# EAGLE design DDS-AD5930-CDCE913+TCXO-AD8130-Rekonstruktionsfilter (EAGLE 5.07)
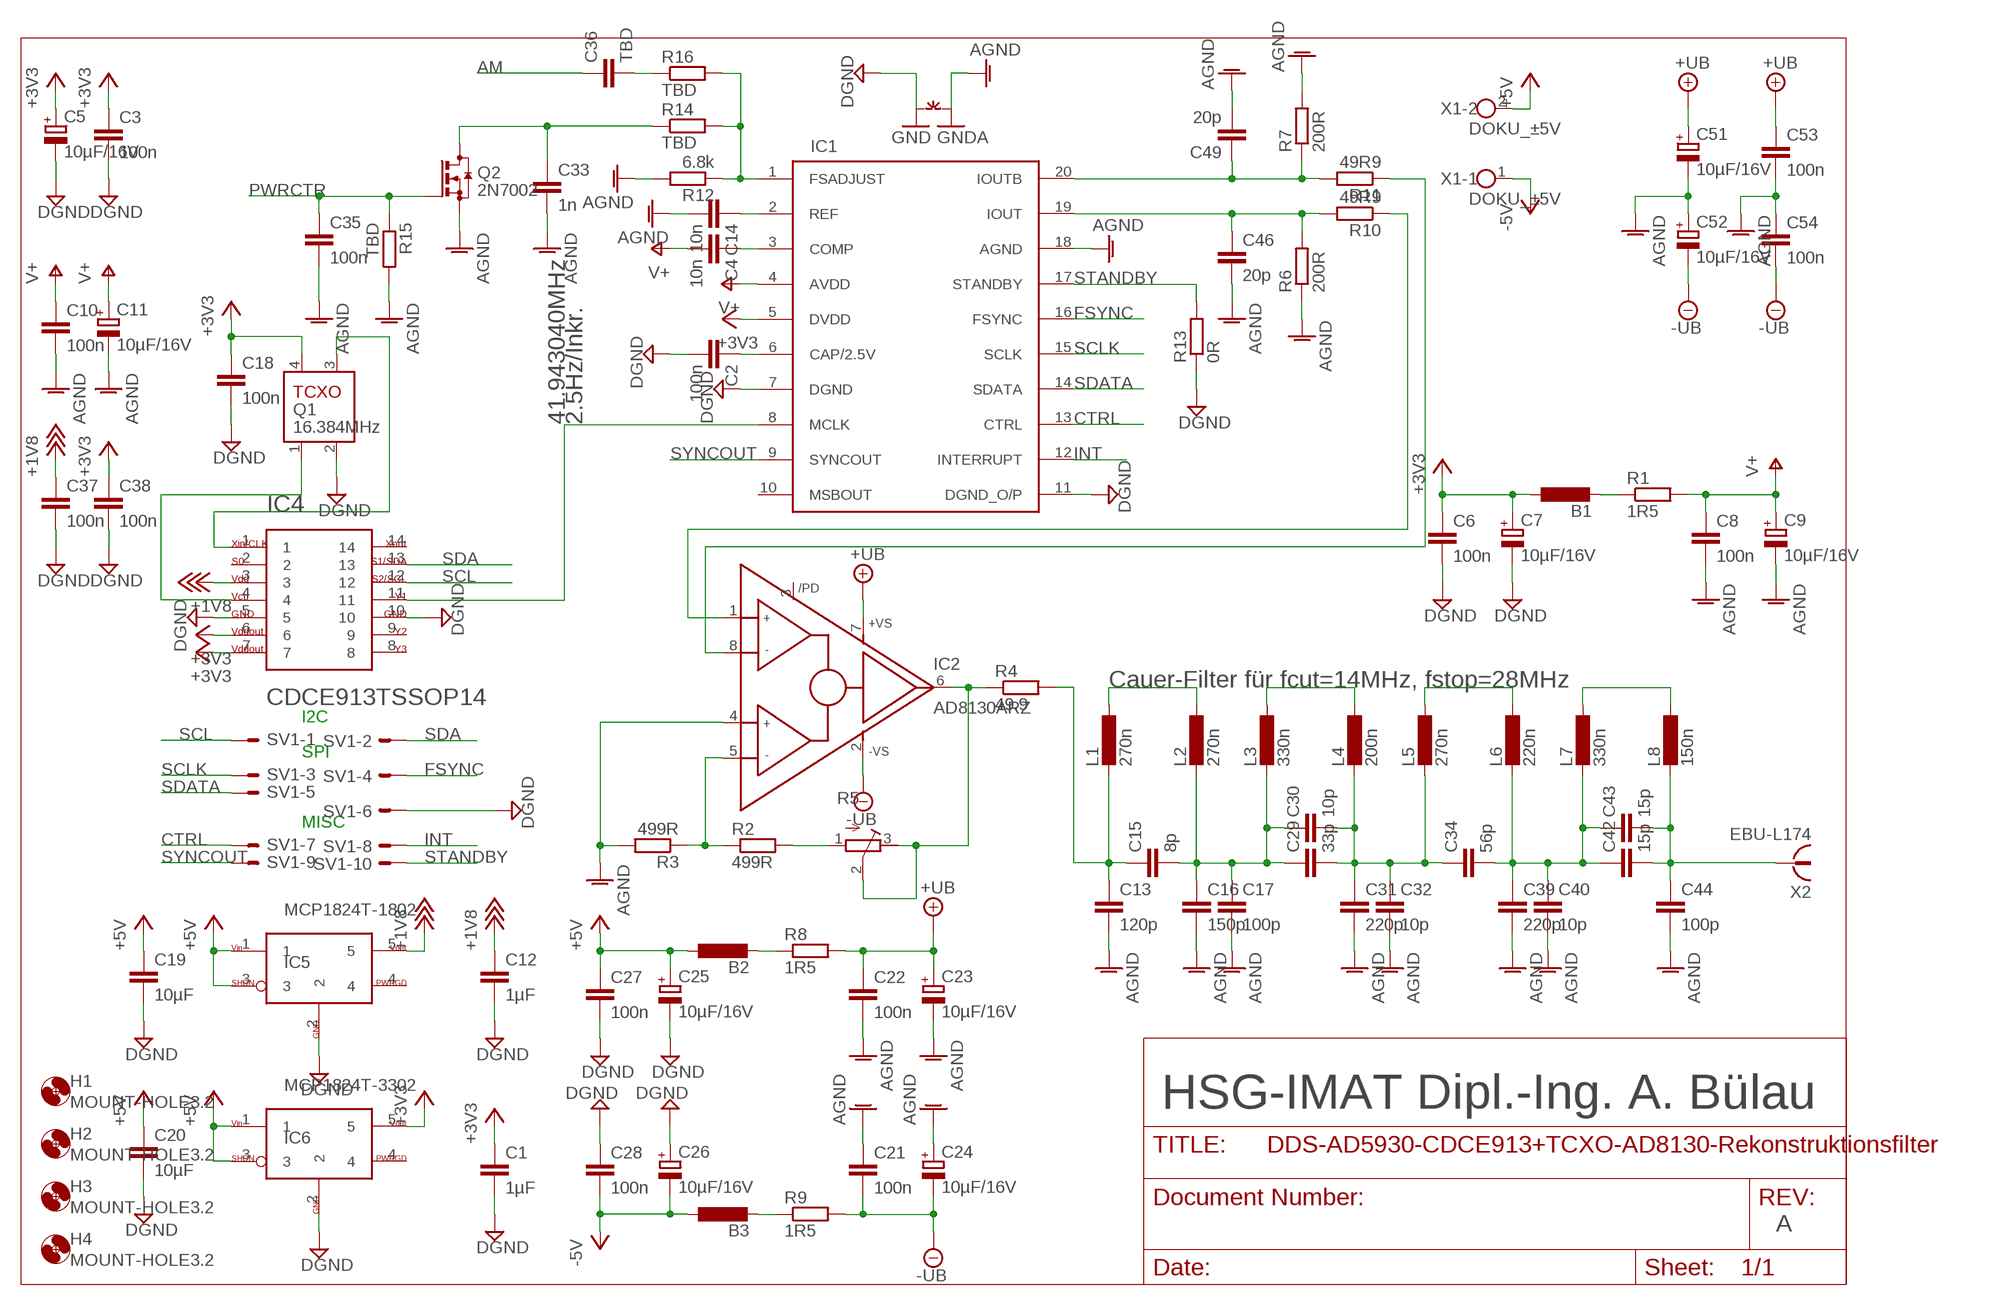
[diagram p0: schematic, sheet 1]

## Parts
B1  FERRITE-BEAD-SMD1206  [L1206]
B2  FERRITE-BEAD-SMD1206  [L1206]
B3  FERRITE-BEAD-SMD1206  [L1206]
C1  1µF  C-EUC0603  [C0603]
C2  100n  C-EUC0603  [C0603]
C3  100n  C-EUC0603  [C0603]
C4  10n  C-EUC0603  [C0603]
C5  10µF/16V  CPOL-EUSMCB  [SMC_B]
C6  100n  C-EUC0603  [C0603]
C7  10µF/16V  CPOL-EUSMCB  [SMC_B]
C8  100n  C-EUC0603  [C0603]
C9  10µF/16V  CPOL-EUSMCB  [SMC_B]
C10  100n  C-EUC0603  [C0603]
C11  10µF/16V  CPOL-EUSMCB  [SMC_B]
C12  1µF  C-EUC0603  [C0603]
C13  120p  C-EUC0805  [C0805]
C14  10n  C-EUC0603  [C0603]
C15  8p  C-EUC0805  [C0805]
C16  150p  C-EUC0805  [C0805]
C17  100p  C-EUC0805  [C0805]
C18  100n  C-EUC0603  [C0603]
C19  10µF  C-EUC0603  [C0603]
C20  10µF  C-EUC0603  [C0603]
C21  100n  C-EUC0603  [C0603]
C22  100n  C-EUC0603  [C0603]
C23  10µF/16V  CPOL-EUSMCB  [SMC_B]
C24  10µF/16V  CPOL-EUSMCB  [SMC_B]
C25  10µF/16V  CPOL-EUSMCB  [SMC_B]
C26  10µF/16V  CPOL-EUSMCB  [SMC_B]
C27  100n  C-EUC0603  [C0603]
C28  100n  C-EUC0603  [C0603]
C29  33p  C-EUC0805  [C0805]
C30  10p  C-EUC0805  [C0805]
C31  220p  C-EUC0805  [C0805]
C32  10p  C-EUC0805  [C0805]
C33  1n  C-EUC0603  [C0603]
C34  56p  C-EUC0805  [C0805]
C35  100n  C-EUC0603  [C0603]
C36  TBD  C-EUC0603  [C0603]
C37  100n  C-EUC0603  [C0603]
C38  100n  C-EUC0603  [C0603]
C39  220p  C-EUC0805  [C0805]
C40  10p  C-EUC0805  [C0805]
C42  15p  C-EUC0805  [C0805]
C43  15p  C-EUC0805  [C0805]
C44  100p  C-EUC0805  [C0805]
C46  20p  C-EUC0603  [C0603]
C49  20p  C-EUC0603  [C0603]
C51  10µF/16V  CPOL-EUSMCB  [SMC_B]
C52  10µF/16V  CPOL-EUSMCB  [SMC_B]
C53  100n  C-EUC0603  [C0603]
C54  100n  C-EUC0603  [C0603]
H1  MOUNT-HOLE3.2  [3,2]
H2  MOUNT-HOLE3.2  [3,2]
H3  MOUNT-HOLE3.2  [3,2]
H4  MOUNT-HOLE3.2  [3,2]
IC1  AD5930  [TSSOP20]
IC2  AD8130ARZ  [SO8]
IC4  CDCE913TSSOP14  [TSSOP14]
IC5  MCP1824T-1802  MCP1824T  [SOT23-5]
IC6  MCP1824T-3302  MCP1824T  [SOT23-5]
L1  270n  L-EUL1008  [L1008]
L2  270n  L-EUL1008  [L1008]
L3  330n  L-EUL1008  [L1008]
L4  200n  L-EUL1008  [L1008]
L5  270n  L-EUL1008  [L1008]
L6  220n  L-EUL1008  [L1008]
L7  330n  L-EUL1008  [L1008]
L8  150n  L-EUL1008  [L1008]
Q1  16.384MHz  CFPT-126  [CFPT-126]
Q2  2N7002  BSS123  [SOT23]
R1  1R5  R-EU_R0805  [R0805]
R2  499R  R-EU_R0603  [R0603]
R3  499R  R-EU_R0603  [R0603]
R4  49.9  R-EU_R0805  [R0805]
R5  R-TRIMM3314J  [RTRIM3314J]
R6  200R  R-EU_R0603  [R0603]
R7  200R  R-EU_R0603  [R0603]
R8  1R5  R-EU_R0805  [R0805]
R9  1R5  R-EU_R0805  [R0805]
R10  49R9  R-EU_R0603  [R0603]
R11  49R9  R-EU_R0603  [R0603]
R12  6.8k  R-EU_R0603  [R0603]
R13  0R  R-EU_R0603  [R0603]
R14  TBD  R-EU_R0603  [R0603]
R15  TBD  R-EU_R0603  [R0603]
R16  TBD  R-EU_R0603  [R0603]
SV1  ML10E  [ML10]
X1  DOKU_±5V  [DOKU_±5V]
X2  EBU-L174  [SMB_EBU-L174]
~NUDEV~1  GND-GNDAVIA  GND-GNDA  [GND-GNDA]

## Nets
+1V8: C12.1 C37.1 IC4.3 IC5.5
+3V3: B1.1 C1.1 C3.1 C5.+ C6.1 C7.+ C18.1 C38.1 IC1.5(DVDD) IC4.6 IC4.7 IC6.5 Q1.4(+VS)
+5V: B2.1 C19.1 C20.1 C25.+ C27.1 IC5.1 IC5.3 IC6.1 IC6.3 X1.2
+UB: C22.1 C23.+ C51.+ C53.1 IC2.7(+VS) R8.2
-5V: B3.1 C26.- C28.2 X1.1
-UB: C21.2 C24.- C52.- C54.2 IC2.2(-VS) R9.2
AGND: C8.2 C9.- C10.2 C11.- C13.2 C14.2 C16.2 C17.2 C21.1 C22.2 C23.- C24.+ C31.2 C32.2 C33.2 C35.2 C39.2 C40.2 C44.2 C46.2 C49.2 C51.- C52.+ C53.2 C54.1 IC1.18(AGND) IC2.4(REF) Q2.2(S) R3.2 R6.1 R7.2 R12.2 R15.2 ~NUDEV~1.GNDA
AM: C36.1
CTRL: IC1.13(CTRL) SV1.7
DGND: C1.2 C2.2 C3.2 C5.- C6.2 C7.- C12.2 C18.2 C19.2 C20.2 C25.- C26.+ C27.2 C28.1 C37.2 C38.2 IC1.7(DGND) IC1.11(DGND_O/P) IC4.5 IC4.10 IC5.2 IC6.2 Q1.2(GND) R13.1 SV1.6 ~NUDEV~1.GND
FSADJUST: IC1.1(FSADJUST) R12.1 R14.2 R16.2
FSYNC: IC1.16(FSYNC) SV1.4
INT: IC1.12(INTERRUPT) SV1.8
N$1: C13.1 C15.1 L1.2 R4.2
N$2: L1.1 L2.1
N$3: C15.2 C16.1 C17.1 C29.1 C30.1 L2.2 L3.2
N$4: C29.2 C30.2 C31.1 C32.1 C34.1 L4.2 L5.2
N$5: L3.1 L4.1
N$6: L5.1 L6.1
N$7: C33.1 Q2.3(D) R14.1
N$8: B1.2 R1.1
N$9: C2.1 IC1.6(CAP/2.5V)
N$10: IC4.4 Q1.1(VCTR)
N$11: IC1.8(MCLK) IC4.11
N$12: C34.2 C39.1 C40.1 C42.1 C43.1 L6.2 L7.2
N$13: C4.1 IC1.3(COMP)
N$14: B2.2 R8.1
N$15: C49.1 IC1.20(IOUTB) R7.1 R11.2
N$16: L7.1 L8.1
N$17: C46.1 IC1.19(IOUT) R6.2 R10.2
N$18: B3.2 R9.1
N$19: IC2.1(IN+) R10.1
N$20: R2.2 R5.1(E)
N$21: IC2.6(OUT) R4.1 R5.2(S) R5.3(A)
N$22: IC2.8(IN-) R11.1
N$23: IC4.1 Q1.3(OUTPUT)
N$24: C14.1 IC1.2(REF)
N$26: IC2.5(FB) R2.1 R3.1
N$28: C36.2 R16.1
OUT: C42.2 C43.2 C44.1 L8.2 X2.1
PWRCTR: C35.1 Q2.1(G) R15.1
SCL: IC4.12 SV1.1
SCLK: IC1.15(SCLK) SV1.3
SDA: IC4.13 SV1.2
SDATA: IC1.14(SDATA) SV1.5
STANDBY: IC1.17(STANDBY) R13.2 SV1.10
SYNCOUT: IC1.9(SYNCOUT) SV1.9
V+: C4.2 C8.1 C9.+ C10.1 C11.+ IC1.4(AVDD) R1.2
Unconnected: IC1.10(MSBOUT) IC2.3(/PD) IC4.2 IC4.8 IC4.9 IC4.14 IC5.4 IC6.4

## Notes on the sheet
- 41.943040MHz | 2.5Hz/Inkr.
- Cauer-Filter für fcut=14MHz, fstop=28MHz
- I2C
- SPI
- MISC
- HSG-IMAT Dipl.-Ing. A. Bülau
- A

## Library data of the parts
B1-B3 = rcl:FERRITE-BEAD-SMD
C1-C4 C6 C8 C10 C12-C22 C27-C40 C42-C44 C46 C49 C53 C54 = rcl:C-EU: CAPACITOR, European symbol
C5 C7 C9 C11 C23-C26 C51 C52 = rcl:CPOL-EU: POLARIZED CAPACITOR, European symbol
H1-H4 = holes:MOUNT-HOLE: MOUNTING HOLE with drill center marker
IC1 = ad5930:AD5930
IC2 = AD8130:AD8130: Differential Receiver Amplifier
IC4 = CDCE913:CDCE913: Programmable 1-PLL VCXO Clock Synthesizer With 1.8-V, 2.5-V and 3.3-V-Outputs
IC5 IC6 = MCP1824:MCP1824: 300mA, Low Voltage, Low Quiescent Current LDO Regulator
L1-L8 = rcl:L-EU: INDUCTOR, European symbol
Q1 = TCXO:CFPT-126: IQD FREQUENCY PRODUCTS TCVCXO
Q2 = transistor-small-signal:BSS123: N-CHANNEL MOS FET
R1-R4 R6-R16 = rcl:R-EU_: RESISTOR, European symbol
R5 = rcl:R-TRIMM: Trimm resistor
SV1 = con-ml:ML10E: HARTING
X1 = Spannungsdurchführung:DOKU_±5V
X2 = SMB-Reichelt:EBU-L174: Löt-Einbaubuchse
~NUDEV~1 = supply-dummy:GND-GNDA: Example of GND--GNDA NET-Connetor for more info read description in package

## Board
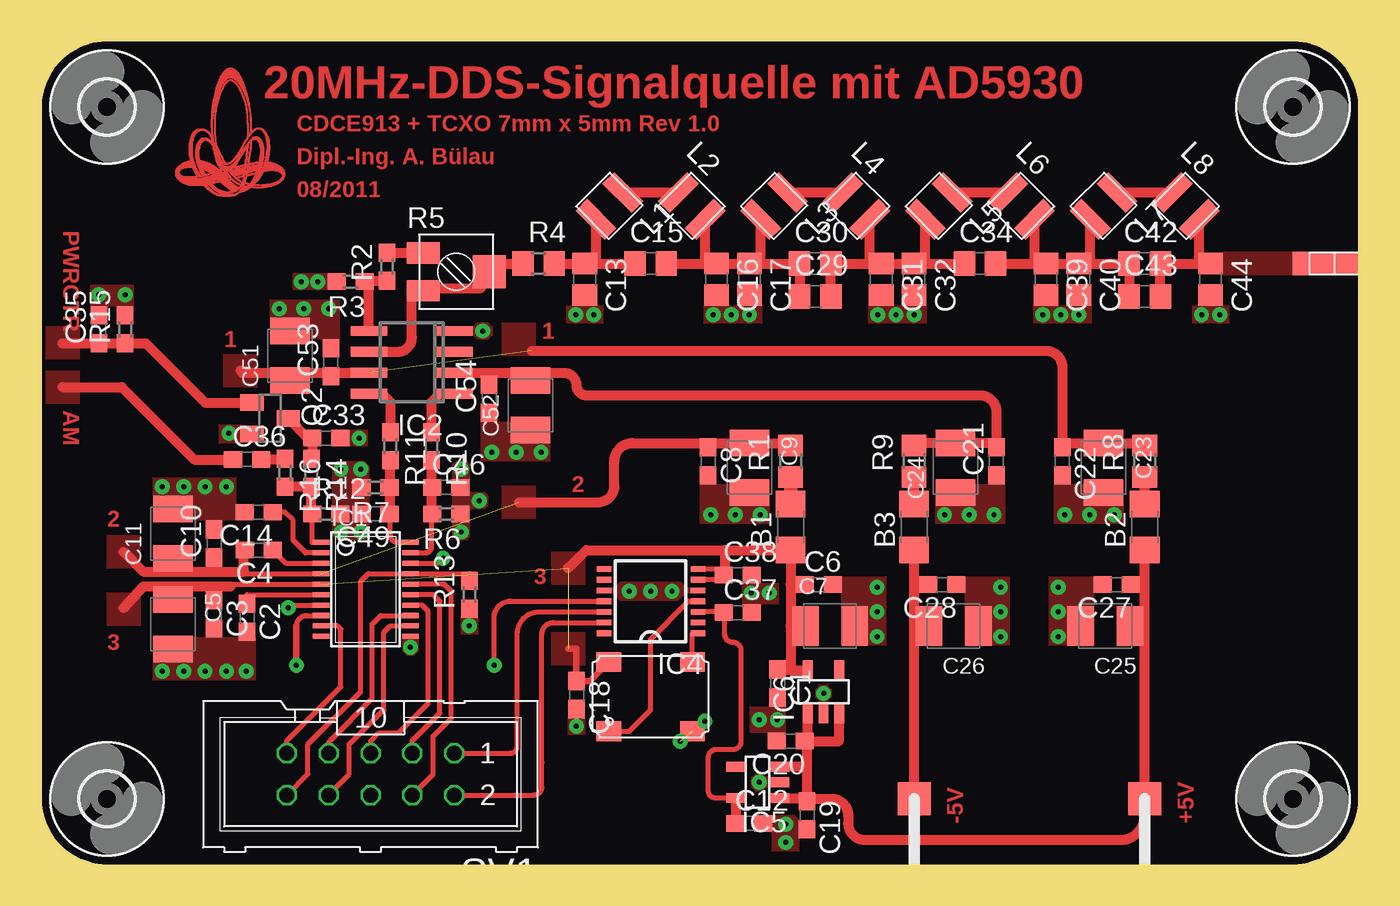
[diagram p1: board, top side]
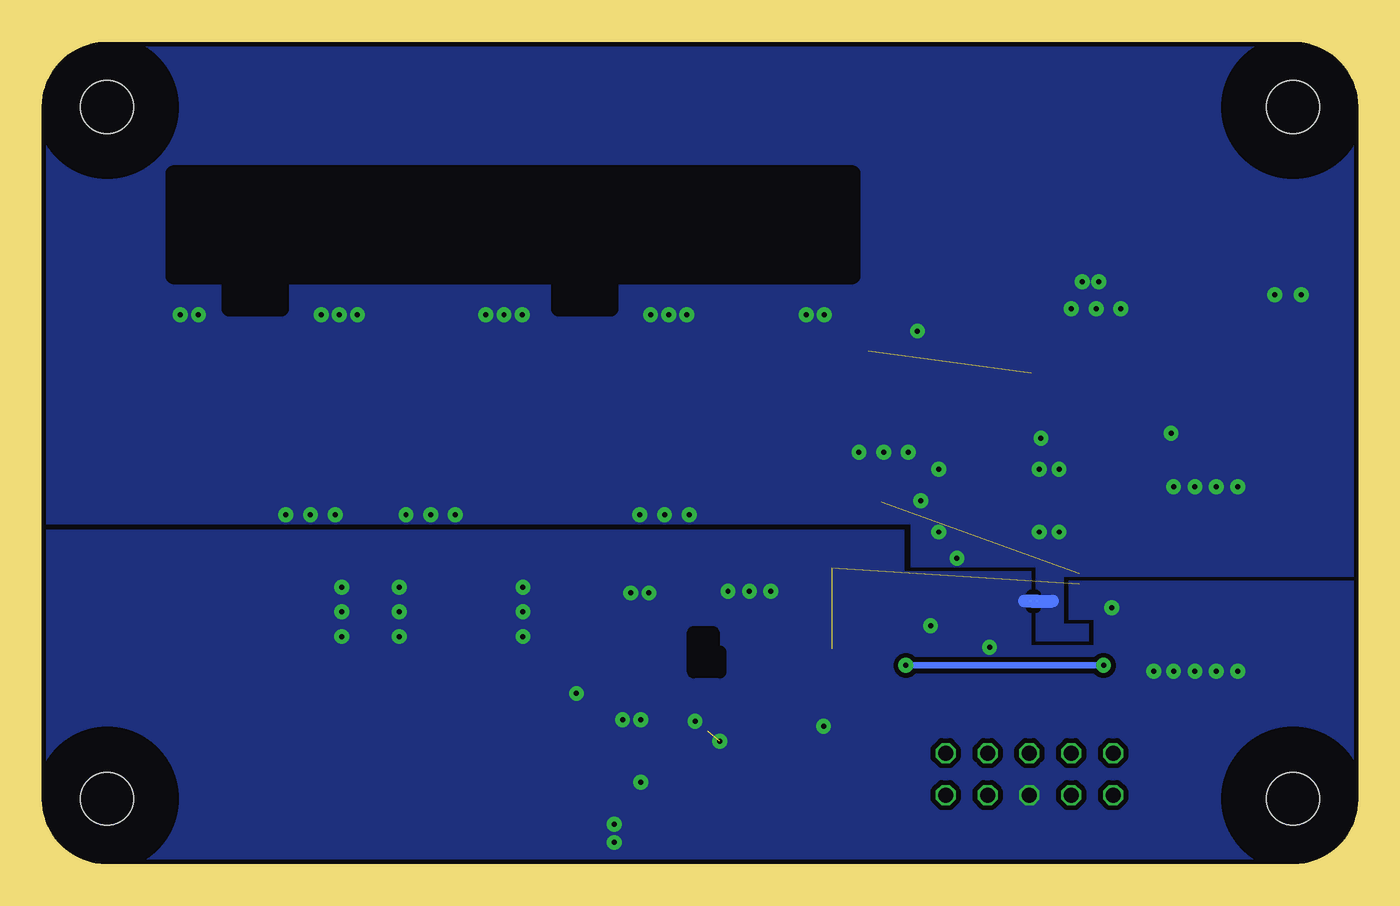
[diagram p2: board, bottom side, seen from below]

Size 80 x 50 mm. Coordinates in mm from the lower left corner, seen from the top.
Outline: 0,4 arc90 4,0 76,0 arc90 80,4 80,46 arc90 76,50 4,50 arc90 0,46 0,4
Copper layers (1*16): Top 0.035mm / dielectric 0.8mm / Bottom 0.035mm
Design rules "A. BÃ¼lau *": minimum track width 0.15mm, minimum drill 0.3mm, track to track 0.3mm, track to pad 0.15mm, pad to pad 0mil, via to via 0.15mm, smd to smd 0mil, copper to edge 0.1mm, drill to drill 0.3mm, minimum pad ring 0.15mm, minimum via ring 0.15mm, stop-mask expansion 0.3mm, vias tented up to drill 0.3mm, thermal gap 10mil
bRestrict: area 30.7,33.8 to 72,42; area 38.8,11.7 to 40.4,14.1
Milling: 8 lines

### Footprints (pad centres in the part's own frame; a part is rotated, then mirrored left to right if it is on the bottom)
L1206 = smd 1.6 x 1.8: 1 -1.4,0; 2 1.4,0
C0603 = smd 1.1 x 1: 1 -0.85,0; 2 0.85,0
SMC_B = smd 1.6 x 2.4: + -1.5,0; - 1.5,0
C0805 = smd 1.3 x 1.5: 1 -0.95,0; 2 0.95,0
3,2 = hole 3.2: 0,0
TSSOP20 = smd 0.305 x 0.991: 1 -3.175,-2.718; 2 -2.54,-2.718; 3 -1.905,-2.718; 4 -1.27,-2.718; 5 -0.635,-2.718; 6 0,-2.718; 7 0.635,-2.718; 8 1.27,-2.718; 9 1.905,-2.718; 10 2.54,-2.718; 11 2.54,2.718; 12 1.905,2.718; 13 1.27,2.718; 14 0.635,2.718; 15 0,2.718; 16 -0.635,2.718; 17 -1.27,2.718; 18 -1.905,2.718; 19 -2.54,2.718; 20 -3.175,2.718
SO8 = smd 0.6 x 2.2: 1 -1.905,-2.6; 2 -0.635,-2.6; 3 0.635,-2.6; 4 1.905,-2.6; 5 1.905,2.6; 6 0.635,2.6; 7 -0.635,2.6; 8 -1.905,2.6
TSSOP14 = smd 0.9 x 0.35: 1 -2.875,1.95; 2 -2.875,1.3; 3 -2.875,0.65; 4 -2.875,0; 5 -2.875,-0.65; 6 -2.875,-1.3; 7 -2.875,-1.95; 8 2.825,-1.95; 9 2.825,-1.3; 10 2.825,-0.65; 11 2.825,0; 12 2.825,0.65; 13 2.825,1.3; 14 2.825,1.95
SOT23-5 = smd 0.6 x 1.2: 1 -0.95,-1.306; 2 0,-1.306; 3 0.95,-1.306; 4 0.95,1.306; 5 -0.95,1.306
L1008 = smd 1 x 2.5: 1 -1.15,0; 2 1.15,0
CFPT-126 = smd 1.5 x 1.2: 1 -2.54,-2.1; 2 2.54,-2.1; 3 2.54,2.1; 4 -2.54,2.1
SOT23 = smd 1 x 1.4: 1 -0.95,-1.1; 2 0.95,-1.1; 3 0,1.1
R0805 = smd 1.3 x 1.5: 1 -0.95,0; 2 0.95,0
R0603 = smd 1.1 x 1: 1 -0.85,0; 2 0.85,0
RTRIM3314J = smd 1.3 x 2: 1 -1.15,-2; 3 1.15,-2 | smd 2 x 2: 2 0,2
ML10 = drill 0.914 octagon: 1 -5.08,-1.27; 2 -5.08,1.27; 3 -2.54,-1.27; 4 -2.54,1.27; 5 0,-1.27; 6 0,1.27; 7 2.54,-1.27; 8 2.54,1.27; 9 5.08,-1.27; 10 5.08,1.27
DOKU_±5V = smd 2 x 2: 1 0,-7; 2 0,7
SMB_EBU-L174 = smd 4 x 1.44: 1 -2,0
GND-GNDA = smd 0.1 x 0.1: GND 0.25,0; GNDA -0.15,0

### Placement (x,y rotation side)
B1  45.5,20.5 90 top
B2  67,20.5 90 top
B3  53,20.5 90 top
C1  44.7,11 270 top
C2  12.5,15 270 top
C3  10.5,15.2 270 top
C4  13.2,19.1 180 top
C5  8,14.6 270 top
C6  47.2,17 0 top
C7  47.9,14.5 0 top
C8  40.5,24.5 270 top
C9  43,24.1 270 top
C10  10.5,19.5 90 top
C11  8,20.1 90 top
C12  43,2.5 0 top
C13  33,35.55 270 top
C14  13.2,21.4 180 top
C15  37,36.5 0 top
C16  41,35.55 270 top
C17  43,35.55 270 top
C18  32.5,10.3 270 top
C19  46.5,3 270 top
C20  45.5,7.5 180 top
C21  58,24.5 90 top
C22  62,24.5 270 top
C23  64.5,24.1 270 top
C24  55.5,24.1 90 top
C25  64.6,14.5 180 top
C26  55.4,14.5 180 top
C27  65.3,17 180 top
C28  54.7,17 180 top
C29  47,34.5 0 top
C30  47,36.5 0 top
C31  51,35.55 270 top
C32  53,35.55 270 top
C33  17.3,25.9 0 top
C34  57,36.5 0 top
C35  3.5,32.5 90 top
C36  12.5,24.6 0 top
C37  42.3,15.3 0 top
C38  42.3,17.6 0 top
C39  61,35.55 270 top
C40  63,35.55 270 top
C42  67,36.5 0 top
C43  67,34.5 0 top
C44  71,35.55 270 top
C46  24.6,22.9 0 top
C49  20.3,21.3 180 top
C51  15.1,30.9 90 top
C52  29.7,27.9 90 top
C53  17.6,30.5 90 top
C54  27.2,28.3 90 top
H1  4,4 90 top
H2  4,46 90 top
H3  76,46 90 top
H4  76,4 90 top
IC1  19.7,16.4 270 top
IC2  22.5,30.5 90 top
IC4  37,16 180 top
IC5  43.5,5 90 top
IC6  47.5,10.5 0 top
L1  34.5,40 225 top
L2  39.5,40 315 top
L3  44.5,40 225 top
L4  49.5,40 315 top
L5  54.5,40 225 top
L6  59.5,40 315 top
L7  64.5,40 225 top
L8  69.5,40 315 top
Q1  37,10.2 0 top
Q2  13.9,27.1 270 top
R1  45.5,24.5 90 top
R2  21,36.3 90 top
R3  18.8,35.4 180 top
R4  30.2,36.5 0 top
R5  25.2,36 270 top
R6  24.6,21.3 180 top
R7  20.3,22.9 180 top
R8  67,24.5 90 top
R9  53,24.5 90 top
R10  23.7,25.4 270 top
R11  21.2,25.4 270 top
R12  17.3,21.3 0 top
R13  26,16.4 90 top
R14  16.4,23.8 270 top
R15  5.1,32.5 90 top
R16  14.8,23.8 270 top
SV1  20,5.5 180 top
U$1  [LOGO]  8,40.5 0 top
X1  60,4 270 top
X2  80,36.5 0 top
~NUDEV~1  19.7,16 180 bottom

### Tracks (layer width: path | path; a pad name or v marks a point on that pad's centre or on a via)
+1V8
  Top 0.305: C37.1 41.65,15.06 | C37.1 41.65,15.04 | IC5.5 40.95,4.05 arc-90 40.5,4.5 40.5,6.5 arc-90 41,7 42,7 arc90 42.5,7.5 42.5,13 arc90 42,13.5 arc-90 41.5,14 41.5,15.3 C37.1 | IC4.3 41.65,15.35 C37.1
  Top 0.61: C12.1 42.19,2.5 IC5.5
+3V3  (2 unrouted)
  Top 0.305: 10.5,16.9 10.5,16.91 | 11.52,17.02 arc90 11.5,16.9 11.5,17.04 IC1.5 | IC4.6 41.45,17.3 C38.1 41.45,17.95 IC4.7
  Top 0.406: Q1.4 33.31,11.15 C18.1 32.5,13.1 32,13.1
  Top 0.61: 45.5,17 45.5,14.5 | 45.5,17 B1.1 41.5,19.1 | 45.5,11.81 IC6.5 | 45.5,14.5 45.5,11.81 | 45.5,14.5 C7.+ | 45.5,17 C6.1 | 45.5,11.81 44.7,11.81 C1.1 | 10.5,16.9 C3.1 | 8,16.9 C5.+ | 8,16.9 10.5,16.9 | 10.5,16.9 11.5,16.9 | 8,16.9 6.2,16.9 5,15.6 | 41.5,19.1 33.1,19.1 32,18 | C38.1 41.5,17.6 41.5,19.1
  Top 0.813: C7.+ 46.4,14.45
  pour Top (no thermals): 31,19 33,19 33,17 31,17
  pour Top (no thermals): 4,16.5 6,16.5 6,14.5 4,14.5
  pour Top (no thermals): 31,14.1 33,14.1 33,12.1 31,12.1
+5V
  Top 0.406: 46.56,7.46 C20.1 46.3,7.46
  Top 0.61: 67,14.5 X1.2 67,3 arc-90 65.5,1.5 50,1.5 arc-90 49,2.5 49,3 arc90 48,4 46.5,4 C19.1 | 67,14.5 67,17 | 67,17 B2.1 | 67,14.5 C25.+ | 67,17 C27.1 | IC5.1 46.5,4.05 C19.1 | 46.5,5.95 IC5.3 | 46.5,5.95 46.5,7.5 C20.1 | IC6.1 46.55,7.5 C20.1 | IC6.3 48.45,7.5 C20.1 | C19.1 46.5,5.95
+UB  (1 unrouted)
  Top 0.61: 67,25.5 R8.2 67,25.6 C23.+ 62,25.6 C22.1 62,30.2 arc90 61,31.2 34.5,31.2 34.4,31.2 29.8,31.2 | 15.1,29.86 17.3,29.86 17.6,29.86 | 15.1,29.86 12.23,29.86 12.1,30 | 15.1,29.86 C51.+ | 17.6,29.86 C53.1 | 17.6,29.86 IC2.7
  pour Top (no thermals): 28,32.9 30,32.9 30,30.9 28,30.9
  pour Top (no thermals): 11.1,29 11.1,31 13.1,31 13.1,29
-5V
  Top 0.61: X1.1 53,14.5 | 53,14.5 53,17 | 53,17 B3.1 | 53,17 C28.2 | 53,14.5 C26.-
-UB
  Top 0.61: C21.2 58,25.5 | C21.2 58,27.5 arc90 57,28.5 33.1,28.5 arc-90 32.5,29.1 arc90 31.73,29.86 29.7,29.86 | R9.2 53,25.6 C24.- 58,25.6 C21.2 | IC2.2 27.2,29.86 | 27.2,29.86 C54.2 | 29.7,29.86 C52.- | 27.2,29.86 29.7,29.86
AGND  (via drill 0.3 pad 0.9)
  Top 0.305: IC1.18 24.11,18.3 v24.4,18.6
  Bottom 0.8: ~NUDEV~1.GNDA 18.6,16
  other vias: 60.8,33.4 61.9,33.4 63,33.4 40.8,33.4 41.9,33.4 43,33.4 50.8,33.4 51.9,33.4 53,33.4 32.45,33.4 33.55,33.4 54.85,21.25 56.35,21.25 57.85,21.25 62.15,21.25 63.65,21.25 65.15,21.25 11.25,22.95 9.95,22.95 8.65,22.95 7.35,22.95 26.8,32.4 70.45,33.4 71.55,33.4 16.8,35.4 15.8,35.4 18.2,24 19.4,24 18.2,20.2 19.4,20.2 17.45,33.75 15.95,33.75 14.45,33.75 27.35,25.05 28.85,25.05 30.35,25.05 40.65,21.25 42.15,21.25 43.65,21.25 25.5,24 25.5,20.2 26.6,22.1 19.3,25.9 3.5,34.6 5.1,34.6 11.4,26.2
  pour Bottom (isolate 0.3, no thermals): 0,50 80,50 80,20.7 27.2,20.7 27.2,18.1 19.6,18.1 19.6,13.6 16.4,13.6 16.4,14.6 17.9,14.6 17.9,17.5 0,17.5
  pour Top (no thermals): 60.26,33.95 63.75,33.95 63.75,32.86 60.26,32.86
  pour Top (no thermals): 40.26,33.95 43.75,33.95 43.75,32.86 40.26,32.86
  pour Top (no thermals): 50.26,33.95 53.75,33.95 53.75,32.87 50.26,32.86
  pour Top (no thermals): 31.91,33.95 34.09,33.95 34.09,32.86 31.91,32.86
  pour Top (no thermals): 54.31,21.8 56.7,21.8 56.7,23.1 58.49,23.1 58.49,20.71 54.31,20.71
  pour Top (no thermals): 61.51,23.1 63.3,23.1 63.3,21.8 65.69,21.8 65.69,20.71 61.51,20.71
  pour Top (no thermals): 11.8,20.9 9.2,20.9 9.2,22.4 6.81,22.4 6.81,23.49 11.8,23.49
  pour Top (no thermals): 69.91,33.95 72.09,33.95 72.09,32.86 69.91,32.86
  pour Top (isolate 0.3, no thermals): 15.3,35.9 17.4,35.9 17.4,34.9 15.3,34.9
  pour Top (isolate 0.3, no thermals): 17.7,23.4 17.7,24.2 18,24.5 19.6,24.5 19.9,24.2 19.9,20 19.6,19.7 18,19.7 17.7,20
  pour Top (no thermals): 18.09,31.9 16.3,31.9 16.3,33.2 13.91,33.2 13.91,34.29 18.09,34.29
  pour Top (no thermals): 26.71,26.9 28.5,26.9 28.5,25.6 30.89,25.6 30.89,24.51 26.71,24.51
  pour Top (no thermals): 40.01,23.1 41.8,23.1 41.8,21.8 44.19,21.8 44.19,20.71 40.01,20.71
  pour Top (isolate 0.3, no thermals): 26.2,32.7 26.3,32.7 26.5,32.9 27.1,32.9 27.3,32.7 27.4,32.7 27.4,32.1 27.3,32.1 27.1,31.9 26.5,31.9 26.3,32.1 26.2,32.1
  pour Top (isolate 0.3, no thermals): 25,19.9 25,24.3 25.2,24.5 25.8,24.5 26,24.3 26,22.7 26.1,22.6 26.9,22.6 27.1,22.4 27.1,21.8 26.9,21.6 26.1,21.6 26,21.5 26,19.9 25.8,19.7 25.2,19.7
  pour Top (isolate 0.3, no thermals): 19.8,25.4 18.7,25.4 18.7,26.4 19.8,26.4
  pour Top (no thermals): 3,33.9 3,35.2 5.6,35.2 5.6,33.9
  pour Top (no thermals): 12.1,26.7 12.1,25.6 10.8,25.6 10.8,26.7
AM
  Top 0.61: 1.3,29 4.9,29 9.3,24.6 C36.1
  pour Top (no thermals): 0.3,28 0.3,30 2.3,30 2.3,28
CTRL
  Top 0.305: IC1.13 20.63,15.13 20.1,14.6 20.1,10.1 17.6,7.6 17.46,7.46 SV1.7
DGND  (via drill 0.3 pad 0.9)  (1 unrouted)
  Top 0.305: IC1.7 15.16,15.77 v15,15.6
  Bottom 0.8: ~NUDEV~1.GND 20.3,16
  other vias: 58.25,13.85 58.25,15.35 58.25,16.85 61.75,16.85 61.75,15.35 61.75,13.85 50.75,13.85 50.75,15.35 50.75,16.85 43.1,16.5 44.2,16.5 43.6,8.8 44.7,8.8 45.2,2.45 45.2,1.35 7.35,11.75 8.65,11.75 9.95,11.75 11.25,11.75 12.45,11.75 35.7,16.6 37,16.6 38.3,16.6 43.6,5 38.8,7.5 40.3,8.7 22.42,13.21 26,14.5 47.5,10.4 32.5,8.4
  pour Bottom (isolate 0.3, no thermals): 0,17.2 17.6,17.2 17.6,14.9 16.1,14.9 16.1,13.3 19.9,13.3 19.9,17.8 27.6,17.8 27.6,20.3 80,20.3 80,0 0,0
  pour Top (no thermals): 56.1,13.31 56.1,17.49 58.79,17.49 58.79,13.31
  pour Top (no thermals): 63.91,13.31 61.21,13.31 61.21,17.49 63.91,17.49
  pour Top (no thermals): 48.6,13.31 48.6,17.49 51.29,17.49 51.29,13.31
  pour Top (no thermals): 42.61,17.1 44.74,17.1 44.74,16.49 44.74,15.8 42.61,15.8
  pour Top (no thermals): 45.19,9.6 45.19,8 44.11,8 43.06,8 43.06,8.84 43.06,9.6
  pour Top (no thermals): 44.4,2.99 45.7,2.99 46,2.69 46,0.81 44.4,0.81
  pour Top (no thermals): 6.81,12.3 9.2,12.3 9.2,13.8 12.99,13.8 12.99,11.21 6.81,11.21
  pour Top (no thermals): 34.62,16.82 34.62,16.48 34.74,16.48 35.16,16.06 38.84,16.06 39.26,16.48 39.43,16.48 39.43,16.82 39.16,16.82 38.84,17.14 35.16,17.14 34.84,16.82
  pour Top (isolate 0.3, no thermals): 25.5,15 26.5,15 26.5,14 25.5,14
  pour Top (isolate 0.3, no thermals): 44.21,5.3 44,5.3 43.8,5.5 43.4,5.5 43.2,5.3 43.1,5.3 43.1,4.7 43.2,4.7 43.4,4.5 43.8,4.5 44,4.7 44.21,4.7
  pour Top (isolate 0.3, no thermals): 47.8,9.79 47.8,10 48,10.2 48,10.6 47.8,10.8 47.8,10.9 47.2,10.9 47.2,10.8 47,10.6 47,10.2 47.2,10 47.2,9.79
  pour Top (isolate 0.3, no thermals): 21.92,13.71 21.92,13.01 22.22,12.71 22.62,12.71 22.92,13.01 22.92,13.71
  pour Top (isolate 0.3, no thermals): 32,8.9 33,8.9 33,7.9 32,7.9
FSADJUST
  Top 0.305: 16.73,19.57 IC1.1 16.45,19.57 R12.1
  Top 0.61: R12.1 16.4,21.3 R14.2 R16.2
FSYNC
  Top 0.305: IC1.16 24.46,17.04 24.9,16.6 24.9,8.9 23.8,7.8 23.8,5.49 SV1.4
INT
  Top 0.305: SV1.8 17.46,4.26 18.7,5.5 18.7,7.3 20.8,9.4 20.8,14.1 21.2,14.49 IC1.12
N$1
  Top 0.61: R4.2 C13.1 33.69,36.5 | 33.69,36.5 L1.2 | 33.69,36.5 C15.1
N$2
  Top 0.61: L1.1 L2.1
N$3
  Top 0.61: C29.1 C30.1 43.69,36.5 | 40.31,36.5 L2.2 | C15.2 40.31,36.5 | 43.69,36.5 L3.2 | 40.31,36.5 C16.1 C17.1 43.69,36.5
N$4
  Top 0.61: C29.2 C30.2 50.31,36.5 50.31,36.6 | 50.31,36.6 L4.2 | 53.69,36.6 53.69,36.5 C34.1 | 53.69,36.6 L5.2 | 53.69,36.6 53,36.6 C32.1 C31.1 51,36.6 50.31,36.6
N$5
  Top 0.61: L3.1 L4.1
N$6
  Top 0.61: L5.1 L6.1
N$7
  Top 0.61: R14.1 16.45,24.65 C33.1 16.2,25.9 Q2.3
N$8
  Top 0.813: B1.2 R1.1
N$9
  Top 0.305: IC1.6 12.5,16.4 C2.1
N$10
  Top 0.305: IC4.4 39.3,16 37,13.7 37,9.4 35.7,8.1 Q1.1
N$11  (via drill 0.3 pad 0.9)
  Top 0.305: IC4.11 28.5,16 arc90 27.5,15 v27.5,12.1 | IC1.8 16.13,15.13 arc90 15.5,14.5
  Top 0.406: v15.5,12.1 15.5,14.5
  Bottom 0.406: v15.5,12.1 v27.5,12.1
N$12
  Top 0.61: C43.1 C42.1 63.69,36.5 | 60.31,36.5 L6.2 | C34.2 60.31,36.5 | 60.31,36.5 C39.1 C40.1 63.69,36.5 | 63.69,36.5 L7.2
N$13
  Top 0.305: IC1.3 14.85,18.3 C4.1
N$14
  Top 0.61: B2.2 R8.1
N$15
  Top 0.305: IC1.20 21.62,19.57 arc-90 21.2,20 21.2,21.3
  Top 0.406: 21.2,21.3 C49.1
  Top 0.61: 21.2,22.9 R11.2 | 21.2,22.9 R7.1 | 21.2,21.3 21.2,22.9
N$16
  Top 0.61: L7.1 L8.1
N$17
  Top 0.305: IC1.19 23.34,18.94 arc90 23.7,19.3 23.7,21.3
  Top 0.406: 23.7,21.3 R6.2
  Top 0.61: 23.7,22.9 R10.2 | 23.7,22.9 C46.1 | 23.7,21.3 23.7,22.9
N$18
  Top 0.61: B3.2 R9.1
N$19
  Top 0.61: IC2.1 24.2,28.59 23.7,28.1 R10.1
N$20
  Top 0.61: R2.2 R5.1
N$21
  Top 0.61: R4.1 27.2,36.5 R5.2 26.7,35 23.7,35 R5.3 22.5,34.85 22.5,32 arc-90 21.64,31.14 IC2.6
N$22
  Top 0.61: IC2.8 20.7,28.59 21.2,28.1 R11.1
N$23
  Top 0.305: IC4.1 39.54,14.05 Q1.3
N$24
  Top 0.305: IC1.2 16.06,18.94 15.3,19.7 15.3,20.9 14.8,21.4 C14.1
N$26
  Top 0.406: IC2.5 19.9,32.7
  Top 0.61: R2.1 19.65,35.45 R3.1 19.9,35.4 19.9,32.7
N$28
  Top 0.61: C36.2 14.8,24.6 R16.1
OUT
  Top 0.61: C43.2 C42.2 70.31,36.5 | 70.31,36.5 L8.2 | 70.31,36.5 C44.1
  pour Top (no thermals): 71.75,37.14 71.82,37.21 76.5,37.21 76.5,35.79 71.82,35.79 71.75,35.86
PWRCTR
  Top 0.61: Q2.1 9.95,28.05 6.35,31.65 R15.1 C35.1 | 1.3,31.65 C35.1 | C35.1 3.5,31.6
  pour Top (no thermals): 2.3,32.7 2.3,30.7 0.3,30.7 0.3,32.7
SCL
  Top 0.305: IC4.12 30.25,15.35 arc90 28.9,14 28.9,8.6 28.9,7.17 arc-90 28.5,6.77 SV1.1
SCLK
  Top 0.305: IC1.15 23.8,16.4 24.2,16 24.2,9.2 22.54,7.54 SV1.3
SDA
  Top 0.305: IC4.13 31.1,14.7 arc90 30.4,14 30.4,6.2 30.4,4.73 arc-90 29.9,4.23 SV1.2
SDATA
  Top 0.305: IC1.14 23.14,15.77 23.5,15.4 23.5,9.8 21.7,8 20.5,8 20,7.5 SV1.5
STANDBY
  Top 0.305: SV1.10 16.2,5.5 16.2,7.3 19.4,10.5 19.4,15.4 | 19.4,15.4 19.4,15.9 | 19.4,15.4 19.4,17.2 19.87,17.67 IC1.17 26,17.67 R13.2
SYNCOUT
  Top 0.305: IC1.9 18,14.49 18.2,14.3 18.2,10.8 14.92,7.52 SV1.9
V+  (1 unrouted)
  Top 0.305: 12.3,17.8 12.3,17.67 | 12.3,17.67 IC1.4 | 12.3,17.67 12.7,17.66
  Top 0.61: R1.2 45.5,25.6 C9.+ 40.5,25.6 | 8,17.8 6.2,17.8 5,19 | 10.5,17.8 12.3,17.8 12.3,19.1 C4.2 | 8,17.8 C11.+ | 10.5,17.8 C10.1 | 8,17.8 10.5,17.8 | 40.5,25.6 35.9,25.6 arc90 34.8,24.5 34.8,23 arc-90 33.8,22 29,22 | 40.5,25.6 C8.1
  pour Top (no thermals): 4,20 6,20 6,18 4,18
  pour Top (no thermals): 28,23 30,23 30,21 28,21

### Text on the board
Top: 20MHz-DDS-Signalquelle mit AD5930 | CDCE913 + TCXO 7mm x 5mm Rev 1.0 | Dipl.-Ing. A. Bülau | 08/2011 | PWRCTR | 1 | 1 | AM | 2 | 2 | 3 | 3 | -5V | +5V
